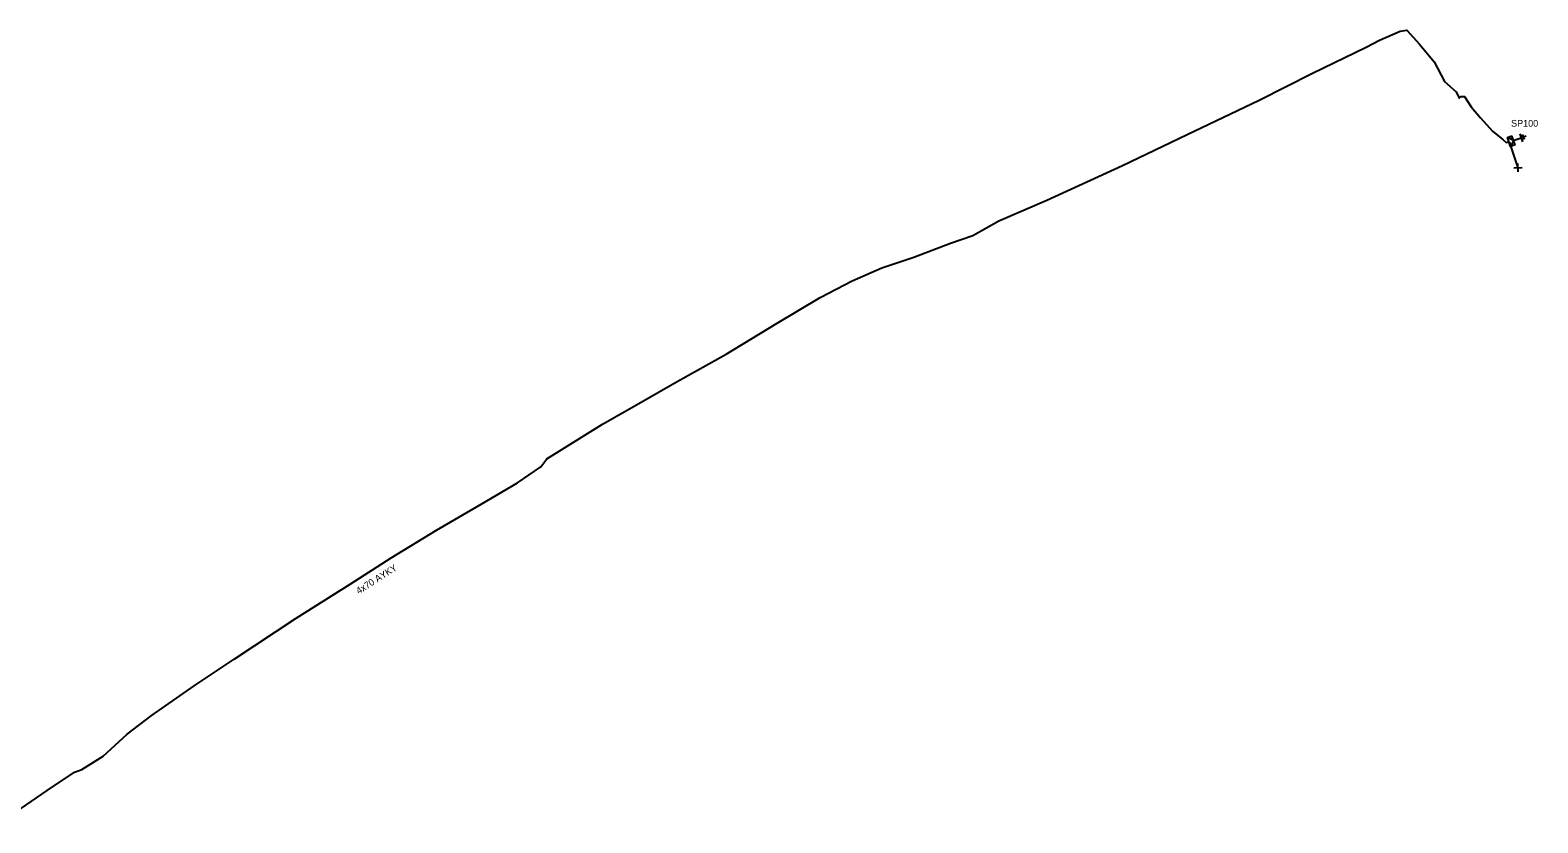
# Model space of a CAD drawing. Extents: x -762500 to -761285, y -1155006 to -1154135.
# Drawn here: x -761506.4 to -761284.6, y -1154458.2 to -1154341.6 of the extents above; entities that cross this region are included whole.
import ezdxf

# ---------------------------------------------------------------- set-up
doc = ezdxf.new("R2010")
doc.units = 0
for name, color, linetype in [('Vrstva 15', 7, 'Continuous'), ('Vrstva 31', 7, 'Continuous'), ('Vrstva 33', 7, 'Continuous'), ('Vrstva 34', 7, 'Continuous'), ('Vrstva 5', 7, 'Continuous'), ('Vrstva 59', 7, 'Continuous'), ('Vrstva 6', 7, 'Continuous')]:
    doc.layers.add(name, color=color, linetype=linetype)

msp = doc.modelspace()

# ---------------------------------------------------------------- linework, layer by layer
at = {"layer": 'Vrstva 15'}
for points in [[(-761288.206, -1154357.828), (-761287.024, -1154357.421)], [(-761287.228, -1154356.83), (-761286.821, -1154358.012)], [(-761286.856, -1154356.957), (-761286.6, -1154357.701)], [(-761286.477, -1154357.092), (-761286.433, -1154357.217)], [(-761286.433, -1154357.217), (-761286.392, -1154357.338)]]:
    msp.add_lwpolyline(points, dxfattribs=at)
at = {"layer": 'Vrstva 31'}
for points in [[(-761287.911, -1154358.461), (-761288.569, -1154358.7), (-761289.048, -1154357.385), (-761288.39, -1154357.145)], [(-761288.151, -1154357.803), (-761289.048, -1154357.385)], [(-761287.911, -1154358.461), (-761288.39, -1154357.145)], [(-761288.151, -1154357.803), (-761288.569, -1154358.7)]]:
    msp.add_lwpolyline(points, dxfattribs=at)
at = {"layer": 'Vrstva 34'}
for points in [[(-761288.115, -1154361.831), (-761286.865, -1154361.809)], [(-761287.479, -1154362.445), (-761287.501, -1154361.195)]]:
    msp.add_lwpolyline(points, dxfattribs=at)
at = {"layer": 'Vrstva 5'}
msp.add_lwpolyline([(-761510.81, -1154458.16), (-761503.91, -1154453.4), (-761499.89, -1154450.72), (-761498.77, -1154450.34), (-761495.64, -1154448.37), (-761492.1, -1154445.11), (-761488.59, -1154442.44), (-761482.25, -1154438), (-761476.37, -1154434.09), (-761467.27, -1154428.05), (-761459.32, -1154423.06), (-761453.3, -1154419.2), (-761446.61, -1154415.14), (-761440.06, -1154411.31), (-761434.67, -1154408.17), (-761431.25, -1154405.8), (-761430.38, -1154404.62), (-761422.17, -1154399.53), (-761416.48, -1154396.3), (-761411.2, -1154393.28), (-761404, -1154389.24), (-761396.48, -1154384.67), (-761390.15, -1154380.93), (-761385.46, -1154378.47), (-761381.07, -1154376.54), (-761376.39, -1154374.97), (-761370.99, -1154372.94), (-761367.69, -1154371.8), (-761363.86, -1154369.63), (-761356.81, -1154366.61), (-761345.69, -1154361.5), (-761336.17, -1154356.96), (-761325.57, -1154351.91), (-761317.71, -1154347.91), (-761309.82, -1154344.1), (-761307.85, -1154343.05), (-761304.85, -1154341.73), (-761303.83, -1154341.6), (-761301.98, -1154343.67), (-761299.8, -1154346.24), (-761298.3, -1154349.14), (-761296.58, -1154350.68), (-761296.13, -1154351.62), (-761295.91, -1154351.36), (-761295.35, -1154351.37), (-761294.4, -1154352.85), (-761293, -1154354.49), (-761291.18, -1154356.5), (-761289.77, -1154357.65), (-761289.21, -1154358.14), (-761288.81, -1154358.04)], dxfattribs=at)
at = {"layer": 'Vrstva 59'}
msp.add_lwpolyline([(-761288.81, -1154358.04), (-761287.49, -1154361.82)], dxfattribs=at)

# ---------------------------------------------------------------- texts
at = {"layer": 'Vrstva 33'}
msp.add_text('SP100', height=0.9943, dxfattribs=at).set_placement((-761288.51, -1154355.79))
at = {"layer": 'Vrstva 6'}
msp.add_text('4x70 AYKY', height=0.9943, rotation=32.54769, dxfattribs=at).set_placement((-761458.04, -1154424.57))

doc.saveas('drawing.dxf')
